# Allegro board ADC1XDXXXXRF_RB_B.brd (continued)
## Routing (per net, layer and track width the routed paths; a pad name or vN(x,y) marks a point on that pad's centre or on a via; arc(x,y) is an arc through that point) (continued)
FMC_DCLK_DQD+: length 142.2
  TOP w0.102: v1(121.71,103.76) 122.22,104.25 U5.A9
  SIG3 w0.102: v3(58.34,90.25) 58.17,90.25 58.12,90.3 58.12,107.54 60.91,110.34 118.52,110.34 121.11,107.75 121.11,105.5 122.11,104.5 122.11,103.87 121.99,103.76 v1(121.71,103.76)
  BOTTOM w0.102: FMC.F4 14.48,74.88 48.19,74.88 58.14,84.83 58.14,90.04 v3(58.34,90.25)
FMC_DCLK_DQD-: length 142.1
  TOP w0.102: U5.B9 122.22,103.25 v1(122.71,103.76)
  SIG3 w0.102: v1(122.71,103.76) 122.31,104.15 122.31,104.59 121.31,105.59 121.31,107.83 118.6,110.54 60.82,110.54 57.91,107.63 57.91,90.47 v3(57.68,90.25)
  BOTTOM w0.102: FMC.F5 14.48,75.13 48.08,75.13 57.89,84.94 57.89,90.04 v3(57.68,90.25)
FMC_DI+0: length 142.1
  TOP w0.102: U5.N7 120.2,92.25 v1(119.71,91.75)
  SIG2 w0.102: v3(10.79,96.6) 11.33,97.13 46.08,97.13 46.18,97.03 46.18,95.7 46.4,95.48 46.77,95.48 46.99,95.7 46.99,97.03 47.09,97.13 47.29,97.13 47.4,97.03 47.4,95.7 47.62,95.48 47.99,95.48 48.21,95.7 48.21,97.03 48.31,97.13 48.51,97.13 48.62,97.03 48.62,95.7 48.84,95.48 49.21,95.48 49.43,95.7 49.43,97.03 49.53,97.13 49.73,97.13 49.83,97.03 49.83,95.7 50.06,95.48 50.43,95.48 50.65,95.7 50.65,97.03 50.75,97.13 50.95,97.13 51.05,97.03 51.05,95.7 51.27,95.48 51.65,95.48 51.87,95.7 51.87,97.03 51.97,97.13 52.17,97.13 52.27,97.03 52.27,95.7 52.49,95.48 52.87,95.48 53.09,95.7 53.09,97.03 53.19,97.13 53.39,97.13 53.49,97.03 53.49,95.7 53.71,95.48 54.08,95.48 54.31,95.7 54.31,97.03 54.41,97.13 54.61,97.13 54.71,97.03 54.71,95.7 54.93,95.48 55.3,95.48 55.52,95.7 55.52,97.03 55.63,97.13 55.83,97.13 55.93,97.03 55.93,95.72 56.15,95.5 56.52,95.5 56.74,95.72 56.74,97.03 56.85,97.13 57.05,97.13 57.15,97.03 57.15,95.72 57.37,95.5 57.74,95.5 57.96,95.72 57.96,97.03 58.06,97.13 98.77,97.13 103.75,92.15 119.21,92.15 119.31,92.15 v1(119.71,91.75)
  BOTTOM w0.102: FMC.C22 v3(10.79,96.6)
FMC_DI+1: length 142.1
  TOP w0.102: U5.M6 119.2,93.25 v1(118.71,92.75)
  SIG1 w0.102: v1(118.71,92.75) 118.28,92.75 117.67,92.15 116.54,92.15 116.31,91.92 116.31,91.49 115.96,91.15 115.53,91.15 115.31,90.92 115.31,90.37 115.09,90.14 106.53,90.14 98.27,98.4 93.33,98.4 93.11,98.62 93.11,98.91 93.01,99.01 92.81,99.01 92.7,98.91 92.7,98.62 92.48,98.4 92.11,98.4 91.89,98.62 91.89,98.91 91.79,99.01 91.59,99.01 91.48,98.91 91.48,98.62 91.26,98.4 90.89,98.4 90.67,98.62 90.67,98.91 90.57,99.01 90.37,99.01 90.27,98.91 90.27,98.62 90.05,98.4 89.67,98.4 89.45,98.62 89.45,98.91 89.35,99.01 89.15,99.01 89.05,98.91 89.05,98.62 88.83,98.4 88.45,98.4 88.23,98.62 88.23,98.91 88.13,99.01 87.93,99.01 87.83,98.91 87.83,98.62 87.61,98.4 87.24,98.4 87.01,98.62 87.01,98.91 86.91,99.01 86.71,99.01 86.61,98.91 86.61,98.62 86.39,98.4 86.02,98.4 85.8,98.62 85.8,98.91 85.69,99.01 85.49,99.01 85.39,98.91 85.39,98.62 85.17,98.4 84.8,98.4 84.58,98.62 84.58,98.91 84.47,99.01 84.27,99.01 84.17,98.91 84.17,98.62 83.95,98.4 83.58,98.4 83.36,98.62 83.36,98.91 83.26,99.01 83.05,99.01 82.95,98.91 82.95,98.62 82.73,98.4 82.36,98.4 82.14,98.62 82.14,98.91 82.04,99.01 81.83,99.01 81.73,98.91 81.73,98.62 81.51,98.4 81.14,98.4 80.92,98.62 80.92,98.91 80.82,99.01 80.61,99.01 80.51,98.91 80.51,98.62 80.29,98.4 79.92,98.4 79.7,98.62 79.7,98.91 79.6,99.01 79.39,99.01 79.29,98.91 79.29,98.62 79.07,98.4 78.7,98.4 78.48,98.62 78.48,98.91 78.38,99.01 78.18,99.01 78.07,98.91 78.07,98.62 77.85,98.4 77.48,98.4 77.26,98.62 77.26,98.91 77.16,99.01 76.96,99.01 76.85,98.91 76.85,98.62 76.63,98.4 76.26,98.4 76.04,98.62 76.04,98.91 75.94,99.01 75.74,99.01 75.64,98.91 75.64,98.62 75.41,98.4 75.04,98.4 74.82,98.62 74.82,98.91 74.72,99.01 74.52,99.01 74.42,98.91 74.42,98.62 74.2,98.4 73.82,98.4 73.6,98.62 73.6,98.91 73.5,99.01 73.3,99.01 73.2,98.91 73.2,98.62 72.98,98.4 72.6,98.4 72.38,98.62 72.38,98.91 72.28,99.01 72.08,99.01 71.98,98.91 71.98,98.62 71.76,98.4 71.39,98.4 71.16,98.62 71.16,98.91 71.06,99.01 70.86,99.01 70.76,98.91 70.76,98.62 70.54,98.4 70.17,98.4 69.95,98.62 69.95,98.91 69.84,99.01 69.64,99.01 69.54,98.91 69.54,98.62 69.32,98.4 68.95,98.4 68.73,98.62 68.73,98.91 68.62,99.01 68.42,99.01 68.32,98.91 68.32,98.62 68.1,98.4 67.73,98.4 67.51,98.62 67.51,98.91 67.41,99.01 67.2,99.01 67.1,98.91 67.1,98.62 66.88,98.4 66.51,98.4 66.29,98.62 66.29,98.91 66.19,99.01 65.98,99.01 65.88,98.91 65.88,98.62 65.66,98.4 65.29,98.4 65.07,98.62 65.07,98.91 64.97,99.01 64.76,99.01 64.66,98.91 64.66,98.62 64.44,98.4 64.07,98.4 63.85,98.62 63.85,98.91 63.75,99.01 63.54,99.01 63.44,98.91 63.44,98.62 63.22,98.4 62.85,98.4 62.63,98.62 62.63,98.91 62.53,99.01 62.33,99.01 62.22,98.91 62.22,98.62 62,98.4 61.63,98.4 61.41,98.62 61.41,98.91 61.31,99.01 61.11,99.01 61,98.91 61,98.62 60.78,98.4 60.41,98.4 60.19,98.62 60.19,98.93 60.09,99.03 59.89,99.03 59.79,98.93 59.79,98.62 59.57,98.4 59.19,98.4 58.97,98.62 58.97,98.93 58.87,99.03 58.67,99.03 58.57,98.93 58.57,98.62 58.35,98.4 57.97,98.4 57.75,98.62 57.75,98.93 57.65,99.03 57.45,99.03 57.35,98.93 57.35,98.62 57.13,98.4 56.76,98.4 56.53,98.62 56.53,98.93 56.43,99.03 56.23,99.03 56.13,98.93 56.13,98.62 55.91,98.4 55.54,98.4 55.32,98.62 55.32,98.93 55.21,99.03 55.01,99.03 54.91,98.93 54.91,98.62 54.69,98.4 54.32,98.4 54.1,98.62 54.1,98.93 53.99,99.03 53.79,99.03 53.69,98.93 53.69,98.62 53.47,98.4 53.1,98.4 52.88,98.62 52.88,98.93 52.78,99.03 52.57,99.03 52.47,98.93 52.47,98.62 52.25,98.4 51.88,98.4 51.66,98.62 51.66,98.93 51.56,99.03 51.35,99.03 51.25,98.93 51.25,98.62 51.03,98.4 50.66,98.4 50.44,98.62 50.44,98.93 50.34,99.03 50.13,99.03 50.03,98.93 50.03,98.62 49.81,98.4 49.44,98.4 49.22,98.62 49.22,98.93 49.12,99.03 48.91,99.03 48.81,98.93 48.81,98.62 48.59,98.4 48.22,98.4 48,98.62 48,98.93 47.9,99.03 47.7,99.03 47.59,98.93 47.59,98.62 47.37,98.4 47,98.4 46.78,98.62 46.78,98.93 46.68,99.03 46.48,99.03 46.37,98.93 46.37,98.62 46.15,98.4 17.35,98.4 17.14,98.2 v3(17.14,97.87)
  BOTTOM w0.102: FMC.H22 v3(17.14,97.87)
FMC_DI+2: length 142.1
  TOP w0.102: v1(117.71,91.75) 118.2,92.25 U5.N5
  SIG1 w0.102: v1(117.71,91.75) 117.31,91.35 117.31,90.48 116.98,90.14 116.51,90.14 116.32,89.95 116.32,89.36 116.1,89.14 105.75,89.14 97.76,97.13 95.77,97.13 95.55,97.35 95.55,97.59 95.45,97.69 95.24,97.69 95.14,97.59 95.14,97.35 94.92,97.13 94.55,97.13 94.33,97.35 94.33,97.59 94.23,97.69 94.02,97.69 93.92,97.59 93.92,97.35 93.7,97.13 93.33,97.13 93.11,97.35 93.11,97.59 93.01,97.69 92.81,97.69 92.7,97.59 92.7,97.35 92.48,97.13 92.11,97.13 91.89,97.35 91.89,97.61 91.79,97.71 91.59,97.71 91.48,97.61 91.48,97.35 91.26,97.13 90.89,97.13 90.67,97.35 90.67,97.61 90.57,97.71 90.37,97.71 90.27,97.61 90.27,97.35 90.05,97.13 89.67,97.13 89.45,97.35 89.45,97.61 89.35,97.71 89.15,97.71 89.05,97.61 89.05,97.35 88.83,97.13 88.45,97.13 88.23,97.35 88.23,97.61 88.13,97.71 87.93,97.71 87.83,97.61 87.83,97.35 87.61,97.13 87.24,97.13 87.01,97.35 87.01,97.61 86.91,97.71 86.71,97.71 86.61,97.61 86.61,97.35 86.39,97.13 86.02,97.13 85.8,97.35 85.8,97.61 85.69,97.71 85.49,97.71 85.39,97.61 85.39,97.35 85.17,97.13 84.8,97.13 84.58,97.35 84.58,97.61 84.47,97.71 84.27,97.71 84.17,97.61 84.17,97.35 83.95,97.13 83.58,97.13 83.36,97.35 83.36,97.61 83.26,97.71 83.05,97.71 82.95,97.61 82.95,97.35 82.73,97.13 82.36,97.13 82.14,97.35 82.14,97.61 82.04,97.71 81.83,97.71 81.73,97.61 81.73,97.35 81.51,97.13 81.14,97.13 80.92,97.35 80.92,97.61 80.82,97.71 80.61,97.71 80.51,97.61 80.51,97.35 80.29,97.13 79.92,97.13 79.7,97.35 79.7,97.61 79.6,97.71 79.39,97.71 79.29,97.61 79.29,97.35 79.07,97.13 78.7,97.13 78.48,97.35 78.48,97.61 78.38,97.71 78.18,97.71 78.07,97.61 78.07,97.35 77.85,97.13 77.48,97.13 77.26,97.35 77.26,97.61 77.16,97.71 76.96,97.71 76.85,97.61 76.85,97.35 76.63,97.13 76.26,97.13 76.04,97.35 76.04,97.61 75.94,97.71 75.74,97.71 75.64,97.61 75.64,97.35 75.41,97.13 75.04,97.13 74.82,97.35 74.82,97.61 74.72,97.71 74.52,97.71 74.42,97.61 74.42,97.35 74.2,97.13 73.82,97.13 73.6,97.35 73.6,97.61 73.5,97.71 73.3,97.71 73.2,97.61 73.2,97.35 72.98,97.13 72.6,97.13 72.38,97.35 72.38,97.61 72.28,97.71 72.08,97.71 71.98,97.61 71.98,97.35 71.76,97.13 71.39,97.13 71.16,97.35 71.16,97.61 71.06,97.71 70.86,97.71 70.76,97.61 70.76,97.35 70.54,97.13 70.17,97.13 69.95,97.35 69.95,97.61 69.84,97.71 69.64,97.71 69.54,97.61 69.54,97.35 69.32,97.13 68.95,97.13 68.73,97.35 68.73,97.61 68.62,97.71 68.42,97.71 68.32,97.61 68.32,97.35 68.1,97.13 67.73,97.13 67.51,97.35 67.51,97.61 67.41,97.71 67.2,97.71 67.1,97.61 67.1,97.35 66.88,97.13 66.51,97.13 66.29,97.35 66.29,97.61 66.19,97.71 65.98,97.71 65.88,97.61 65.88,97.35 65.66,97.13 65.29,97.13 65.07,97.35 65.07,97.61 64.97,97.71 64.76,97.71 64.66,97.61 64.66,97.35 64.44,97.13 64.07,97.13 63.85,97.35 63.85,97.61 63.75,97.71 63.54,97.71 63.44,97.61 63.44,97.35 63.22,97.13 62.85,97.13 62.63,97.35 62.63,97.61 62.53,97.71 62.33,97.71 62.22,97.61 62.22,97.35 62,97.13 61.63,97.13 61.41,97.35 61.41,97.61 61.31,97.71 61.11,97.71 61,97.61 61,97.35 60.78,97.13 60.41,97.13 60.19,97.35 60.19,97.61 60.09,97.71 59.89,97.71 59.79,97.61 59.79,97.35 59.57,97.13 59.19,97.13 58.97,97.35 58.97,97.61 58.87,97.71 58.67,97.71 58.57,97.61 58.57,97.35 58.35,97.13 57.97,97.13 57.75,97.35 57.75,97.61 57.65,97.71 57.45,97.71 57.35,97.61 57.35,97.35 57.13,97.13 56.76,97.13 56.53,97.35 56.53,97.61 56.43,97.71 56.23,97.71 56.13,97.61 56.13,97.35 55.91,97.13 55.54,97.13 55.32,97.35 55.32,97.61 55.21,97.71 55.01,97.71 54.91,97.61 54.91,97.35 54.69,97.13 54.32,97.13 54.1,97.35 54.1,97.61 53.99,97.71 53.79,97.71 53.69,97.61 53.69,97.35 53.47,97.13 53.1,97.13 52.88,97.35 52.88,97.61 52.78,97.71 52.57,97.71 52.47,97.61 52.47,97.35 52.25,97.13 51.88,97.13 51.66,97.35 51.66,97.61 51.56,97.71 51.35,97.71 51.25,97.61 51.25,97.35 51.03,97.13 50.66,97.13 50.44,97.35 50.44,97.61 50.34,97.71 50.13,97.71 50.03,97.61 50.03,97.35 49.81,97.13 49.44,97.13 49.22,97.35 49.22,97.61 49.12,97.71 48.91,97.71 48.81,97.61 48.81,97.35 48.59,97.13 48.22,97.13 48,97.35 48,97.61 47.9,97.71 47.7,97.71 47.59,97.61 47.59,97.35 47.37,97.13 47,97.13 46.78,97.35 46.78,97.61 46.68,97.71 46.48,97.71 46.37,97.61 46.37,97.35 46.15,97.13 15.62,97.13 15.49,97 15.49,96.7 15.6,96.6 v3(15.88,96.6)
  BOTTOM w0.102: FMC.G21 v3(15.88,96.6)
FMC_DI+3: length 142.2
  TOP w0.102: U5.M4 117.2,93.25 v1(116.71,92.75)
  SIG1 w0.102: v1(116.71,92.75) 116.29,92.75 115.87,92.33 115.57,92.33 115.39,92.15 108.13,92.15 98.07,102.21 95.77,102.21 95.55,102.43 95.55,102.72 95.45,102.82 95.24,102.82 95.14,102.72 95.14,102.43 94.92,102.21 94.55,102.21 94.33,102.43 94.33,102.72 94.23,102.82 94.02,102.82 93.92,102.72 93.92,102.43 93.7,102.21 93.33,102.21 93.11,102.43 93.11,102.72 93.01,102.82 92.81,102.82 92.7,102.72 92.7,102.43 92.48,102.21 92.11,102.21 91.89,102.43 91.89,102.72 91.79,102.82 91.59,102.82 91.48,102.72 91.48,102.43 91.26,102.21 90.89,102.21 90.67,102.43 90.67,102.72 90.57,102.82 90.37,102.82 90.27,102.72 90.27,102.43 90.05,102.21 89.67,102.21 89.45,102.43 89.45,102.72 89.35,102.82 89.15,102.82 89.05,102.72 89.05,102.43 88.83,102.21 88.45,102.21 88.23,102.43 88.23,102.72 88.13,102.82 87.93,102.82 87.83,102.72 87.83,102.43 87.61,102.21 87.24,102.21 87.01,102.43 87.01,102.72 86.91,102.82 86.71,102.82 86.61,102.72 86.61,102.43 86.39,102.21 86.02,102.21 85.8,102.43 85.8,102.72 85.69,102.82 85.49,102.82 85.39,102.72 85.39,102.43 85.17,102.21 84.8,102.21 84.58,102.43 84.58,102.74 84.47,102.84 84.27,102.84 84.17,102.74 84.17,102.43 83.95,102.21 83.58,102.21 83.36,102.43 83.36,102.74 83.26,102.84 83.05,102.84 82.95,102.74 82.95,102.43 82.73,102.21 82.36,102.21 82.14,102.43 82.14,102.74 82.04,102.84 81.83,102.84 81.73,102.74 81.73,102.43 81.51,102.21 81.14,102.21 80.92,102.43 80.92,102.74 80.82,102.84 80.61,102.84 80.51,102.74 80.51,102.43 80.29,102.21 79.92,102.21 79.7,102.43 79.7,102.74 79.6,102.84 79.39,102.84 79.29,102.74 79.29,102.43 79.07,102.21 78.7,102.21 78.48,102.43 78.48,102.74 78.38,102.84 78.18,102.84 78.07,102.74 78.07,102.43 77.85,102.21 77.48,102.21 77.26,102.43 77.26,102.74 77.16,102.84 76.96,102.84 76.85,102.74 76.85,102.43 76.63,102.21 76.26,102.21 76.04,102.43 76.04,102.74 75.94,102.84 75.74,102.84 75.64,102.74 75.64,102.43 75.41,102.21 75.04,102.21 74.82,102.43 74.82,102.74 74.72,102.84 74.52,102.84 74.42,102.74 74.42,102.43 74.2,102.21 73.82,102.21 73.6,102.43 73.6,102.74 73.5,102.84 73.3,102.84 73.2,102.74 73.2,102.43 72.98,102.21 72.6,102.21 72.38,102.43 72.38,102.74 72.28,102.84 72.08,102.84 71.98,102.74 71.98,102.43 71.76,102.21 71.39,102.21 71.16,102.43 71.16,102.74 71.06,102.84 70.86,102.84 70.76,102.74 70.76,102.43 70.54,102.21 70.17,102.21 69.95,102.43 69.95,102.74 69.84,102.84 69.64,102.84 69.54,102.74 69.54,102.43 69.32,102.21 68.95,102.21 68.73,102.43 68.73,102.74 68.62,102.84 68.42,102.84 68.32,102.74 68.32,102.43 68.1,102.21 67.73,102.21 67.51,102.43 67.51,102.74 67.41,102.84 67.2,102.84 67.1,102.74 67.1,102.43 66.88,102.21 66.51,102.21 66.29,102.43 66.29,102.74 66.19,102.84 65.98,102.84 65.88,102.74 65.88,102.43 65.66,102.21 65.29,102.21 65.07,102.43 65.07,102.74 64.97,102.84 64.76,102.84 64.66,102.74 64.66,102.43 64.44,102.21 64.07,102.21 63.85,102.43 63.85,102.74 63.75,102.84 63.54,102.84 63.44,102.74 63.44,102.43 63.22,102.21 62.85,102.21 62.63,102.43 62.63,102.74 62.53,102.84 62.33,102.84 62.22,102.74 62.22,102.43 62,102.21 61.63,102.21 61.41,102.43 61.41,102.74 61.31,102.84 61.11,102.84 61,102.74 61,102.43 60.78,102.21 60.41,102.21 60.19,102.43 60.19,102.74 60.09,102.84 59.89,102.84 59.79,102.74 59.79,102.43 59.57,102.21 59.19,102.21 58.97,102.43 58.97,102.74 58.87,102.84 58.67,102.84 58.57,102.74 58.57,102.43 58.35,102.21 57.97,102.21 57.75,102.43 57.75,102.74 57.65,102.84 57.45,102.84 57.35,102.74 57.35,102.43 57.13,102.21 56.76,102.21 56.53,102.43 56.53,102.74 56.43,102.84 56.23,102.84 56.13,102.74 56.13,102.43 55.91,102.21 55.54,102.21 55.32,102.43 55.32,102.74 55.21,102.84 55.01,102.84 54.91,102.74 54.91,102.43 54.69,102.21 54.32,102.21 54.1,102.43 54.1,102.74 53.99,102.84 53.79,102.84 53.69,102.74 53.69,102.43 53.47,102.21 53.1,102.21 52.88,102.43 52.88,102.74 52.78,102.84 52.57,102.84 52.47,102.74 52.47,102.43 52.25,102.21 51.88,102.21 51.66,102.43 51.66,102.74 51.56,102.84 51.35,102.84 51.25,102.74 51.25,102.43 51.03,102.21 50.66,102.21 50.44,102.43 50.44,102.74 50.34,102.84 50.13,102.84 50.03,102.74 50.03,102.43 49.81,102.21 49.44,102.21 49.22,102.43 49.22,102.74 49.12,102.84 48.91,102.84 48.81,102.74 48.81,102.43 48.59,102.21 48.22,102.21 48,102.43 48,102.74 47.9,102.84 47.7,102.84 47.59,102.74 47.59,102.43 47.37,102.21 47,102.21 46.78,102.43 46.78,102.74 46.68,102.84 46.48,102.84 46.37,102.74 46.37,102.43 46.15,102.21 17.35,102.21 17.14,102.01 v3(17.14,101.68)
  BOTTOM w0.102: FMC.H25 v3(17.14,101.68)
FMC_DI+4: length 142.1
  TOP w0.102: v1(115.7,91.75) 116.2,92.25 U5.N3
  SIG1 w0.102: v1(115.7,91.75) 115.27,91.75 114.83,91.31 114.56,91.31 114.56,91.31 114.39,91.15 107.45,91.15 97.66,100.94 96.99,100.94 96.77,101.16 96.77,101.45 96.67,101.55 96.46,101.55 96.36,101.45 96.36,101.16 96.14,100.94 95.77,100.94 95.55,101.16 95.55,101.45 95.45,101.55 95.24,101.55 95.14,101.45 95.14,101.16 94.92,100.94 94.55,100.94 94.33,101.16 94.33,101.45 94.23,101.55 94.02,101.55 93.92,101.45 93.92,101.16 93.7,100.94 93.33,100.94 93.11,101.16 93.11,101.45 93.01,101.55 92.81,101.55 92.7,101.45 92.7,101.16 92.48,100.94 92.11,100.94 91.89,101.16 91.89,101.45 91.79,101.55 91.59,101.55 91.48,101.45 91.48,101.16 91.26,100.94 90.89,100.94 90.67,101.16 90.67,101.45 90.57,101.55 90.37,101.55 90.27,101.45 90.27,101.16 90.05,100.94 89.67,100.94 89.45,101.16 89.45,101.45 89.35,101.55 89.15,101.55 89.05,101.45 89.05,101.16 88.83,100.94 88.45,100.94 88.23,101.16 88.23,101.45 88.13,101.55 87.93,101.55 87.83,101.45 87.83,101.16 87.61,100.94 87.24,100.94 87.01,101.16 87.01,101.45 86.91,101.55 86.71,101.55 86.61,101.45 86.61,101.16 86.39,100.94 86.02,100.94 85.8,101.16 85.8,101.45 85.69,101.55 85.49,101.55 85.39,101.45 85.39,101.16 85.17,100.94 84.8,100.94 84.58,101.16 84.58,101.45 84.47,101.55 84.27,101.55 84.17,101.45 84.17,101.16 83.95,100.94 83.58,100.94 83.36,101.16 83.36,101.45 83.26,101.55 83.05,101.55 82.95,101.45 82.95,101.16 82.73,100.94 82.36,100.94 82.14,101.16 82.14,101.45 82.04,101.55 81.83,101.55 81.73,101.45 81.73,101.16 81.51,100.94 81.14,100.94 80.92,101.16 80.92,101.45 80.82,101.55 80.61,101.55 80.51,101.45 80.51,101.16 80.29,100.94 79.92,100.94 79.7,101.16 79.7,101.45 79.6,101.55 79.39,101.55 79.29,101.45 79.29,101.16 79.07,100.94 78.7,100.94 78.48,101.16 78.48,101.45 78.38,101.55 78.18,101.55 78.07,101.45 78.07,101.16 77.85,100.94 77.48,100.94 77.26,101.16 77.26,101.45 77.16,101.55 76.96,101.55 76.85,101.45 76.85,101.16 76.63,100.94 76.26,100.94 76.04,101.16 76.04,101.45 75.94,101.55 75.74,101.55 75.64,101.45 75.64,101.16 75.41,100.94 75.04,100.94 74.82,101.16 74.82,101.45 74.72,101.55 74.52,101.55 74.42,101.45 74.42,101.16 74.2,100.94 73.82,100.94 73.6,101.16 73.6,101.45 73.5,101.55 73.3,101.55 73.2,101.45 73.2,101.16 72.98,100.94 72.6,100.94 72.38,101.16 72.38,101.45 72.28,101.55 72.08,101.55 71.98,101.45 71.98,101.16 71.76,100.94 71.39,100.94 71.16,101.16 71.16,101.45 71.06,101.55 70.86,101.55 70.76,101.45 70.76,101.16 70.54,100.94 70.17,100.94 69.95,101.16 69.95,101.45 69.84,101.55 69.64,101.55 69.54,101.45 69.54,101.16 69.32,100.94 68.95,100.94 68.73,101.16 68.73,101.45 68.62,101.55 68.42,101.55 68.32,101.45 68.32,101.16 68.1,100.94 67.73,100.94 67.51,101.16 67.51,101.45 67.41,101.55 67.2,101.55 67.1,101.45 67.1,101.16 66.88,100.94 66.51,100.94 66.29,101.16 66.29,101.45 66.19,101.55 65.98,101.55 65.88,101.45 65.88,101.16 65.66,100.94 65.29,100.94 65.07,101.16 65.07,101.45 64.97,101.55 64.76,101.55 64.66,101.45 64.66,101.16 64.44,100.94 64.07,100.94 63.85,101.16 63.85,101.45 63.75,101.55 63.54,101.55 63.44,101.45 63.44,101.16 63.22,100.94 62.85,100.94 62.63,101.16 62.63,101.45 62.53,101.55 62.33,101.55 62.22,101.45 62.22,101.16 62,100.94 61.63,100.94 61.41,101.16 61.41,101.45 61.31,101.55 61.11,101.55 61,101.45 61,101.16 60.78,100.94 60.41,100.94 60.19,101.16 60.19,101.47 60.09,101.57 59.89,101.57 59.79,101.47 59.79,101.16 59.57,100.94 59.19,100.94 58.97,101.16 58.97,101.47 58.87,101.57 58.67,101.57 58.57,101.47 58.57,101.16 58.35,100.94 57.97,100.94 57.75,101.16 57.75,101.47 57.65,101.57 57.45,101.57 57.35,101.47 57.35,101.16 57.13,100.94 56.76,100.94 56.53,101.16 56.53,101.47 56.43,101.57 56.23,101.57 56.13,101.47 56.13,101.16 55.91,100.94 55.54,100.94 55.32,101.16 55.32,101.47 55.21,101.57 55.01,101.57 54.91,101.47 54.91,101.16 54.69,100.94 54.32,100.94 54.1,101.16 54.1,101.47 53.99,101.57 53.79,101.57 53.69,101.47 53.69,101.16 53.47,100.94 53.1,100.94 52.88,101.16 52.88,101.47 52.78,101.57 52.57,101.57 52.47,101.47 52.47,101.16 52.25,100.94 51.88,100.94 51.66,101.16 51.66,101.47 51.56,101.57 51.35,101.57 51.25,101.47 51.25,101.16 51.03,100.94 50.66,100.94 50.44,101.16 50.44,101.47 50.34,101.57 50.13,101.57 50.03,101.47 50.03,101.16 49.81,100.94 49.44,100.94 49.22,101.16 49.22,101.47 49.12,101.57 48.91,101.57 48.81,101.47 48.81,101.16 48.59,100.94 48.22,100.94 48,101.16 48,101.47 47.9,101.57 47.7,101.57 47.59,101.47 47.59,101.16 47.37,100.94 47,100.94 46.78,101.16 46.78,101.47 46.68,101.57 46.48,101.57 46.37,101.47 46.37,101.16 46.15,100.94 16.08,100.94 15.88,100.74 v3(15.88,100.41)
  BOTTOM w0.102: FMC.G24 v3(15.88,100.41)
FMC_DI+5: length 142.1
  TOP w0.102: U5.M2 115.2,93.25 v1(114.7,92.75)
  SIG2 w0.102: v1(114.7,92.75) 114.29,92.75 113.69,93.35 104.25,93.35 98.99,98.6 61.72,98.6 61.62,98.7 61.62,99.73 61.4,99.95 61.03,99.95 60.81,99.73 60.81,98.7 60.71,98.6 60.5,98.6 60.4,98.7 60.4,99.73 60.18,99.95 59.81,99.95 59.59,99.73 59.59,98.7 59.49,98.6 59.28,98.6 59.18,98.7 59.18,99.73 58.96,99.95 58.59,99.95 58.37,99.73 58.37,98.7 58.27,98.6 58.06,98.6 57.96,98.7 57.96,99.75 57.74,99.97 57.37,99.97 57.15,99.75 57.15,98.7 57.05,98.6 56.85,98.6 56.74,98.7 56.74,99.75 56.52,99.97 56.15,99.97 55.93,99.75 55.93,98.7 55.83,98.6 55.63,98.6 55.52,98.7 55.52,99.75 55.3,99.97 54.93,99.97 54.71,99.75 54.71,98.7 54.61,98.6 54.41,98.6 54.31,98.7 54.31,99.75 54.08,99.97 53.71,99.97 53.49,99.75 53.49,98.7 53.39,98.6 53.19,98.6 53.09,98.7 53.09,99.75 52.87,99.97 52.49,99.97 52.27,99.75 52.27,98.7 52.17,98.6 51.97,98.6 51.87,98.7 51.87,99.75 51.65,99.97 51.27,99.97 51.05,99.75 51.05,98.7 50.95,98.6 50.75,98.6 50.65,98.7 50.65,99.75 50.43,99.97 50.06,99.97 49.83,99.75 49.83,98.7 49.73,98.6 49.53,98.6 49.43,98.7 49.43,99.75 49.21,99.97 48.84,99.97 48.62,99.75 48.62,98.7 48.51,98.6 48.31,98.6 48.21,98.7 48.21,99.75 47.99,99.97 47.62,99.97 47.4,99.75 47.4,98.7 47.29,98.6 47.09,98.6 46.99,98.7 46.99,99.75 46.77,99.97 46.4,99.97 46.18,99.75 46.18,98.7 46.08,98.6 10.36,98.6 10.2,98.77 10.2,99.55 10.32,99.67 11.53,99.67 v3(12.06,99.14)
  BOTTOM w0.102: v3(12.06,99.14) FMC.D23
FMC_DI+6: length 142.1
  TOP w0.102: U5.L7 120.2,94.24 v1(119.71,93.75)
  SIG3 w0.102: v3(80.04,92.79) 80.08,92.79 80.64,93.35 116.44,93.35 117.44,94.35 119.1,94.35 v1(119.71,93.75)
  BOTTOM w0.102: FMC.H28 17.04,104.32 17.04,103.2 17.42,102.82 45.32,102.82 46.91,104.42 46.91,109.5 47.85,110.44 49.63,110.44 49.73,110.34 49.73,108.86 49.98,108.61 50.4,108.61 50.65,108.86 50.65,110.34 50.75,110.44 50.95,110.44 51.06,110.34 51.06,108.86 51.31,108.61 51.72,108.61 51.97,108.86 51.97,110.34 52.07,110.44 52.27,110.44 52.38,110.34 52.38,108.86 52.63,108.61 53.04,108.61 53.29,108.86 53.29,110.34 53.39,110.44 53.6,110.44 53.7,110.34 53.7,108.86 53.95,108.61 54.36,108.61 54.61,108.86 54.61,110.34 54.71,110.44 54.92,110.44 55.02,110.34 55.02,108.86 55.27,108.61 55.68,108.61 55.93,108.86 55.93,110.34 56.03,110.44 72.87,110.44 80.04,103.28 v3(80.04,92.79)
FMC_DI+7: length 142.2
  TOP w0.102: v1(119.69,94.74) U5.K7
  SIG2 w0.102: v1(119.69,94.74) 119.28,94.74 118.87,94.34 118.57,94.34 118.12,94.78 118.12,95.93 117.9,96.14 104.42,96.14 97.08,103.48 93.34,103.48 93.12,103.7 93.12,103.94 93.01,104.04 92.81,104.04 92.71,103.94 92.71,103.7 92.49,103.48 92.12,103.48 91.9,103.7 91.9,103.94 91.8,104.04 91.59,104.04 91.49,103.94 91.49,103.7 91.27,103.48 90.9,103.48 90.68,103.7 90.68,103.94 90.58,104.04 90.37,104.04 90.27,103.94 90.27,103.7 90.05,103.48 89.68,103.48 89.46,103.7 89.46,103.94 89.36,104.04 89.15,104.04 89.05,103.94 89.05,103.7 88.83,103.48 88.46,103.48 88.24,103.7 88.24,103.94 88.14,104.04 87.93,104.04 87.83,103.94 87.83,103.7 87.61,103.48 87.24,103.48 87.02,103.7 87.02,103.96 86.92,104.06 86.72,104.06 86.61,103.96 86.61,103.7 86.39,103.48 86.02,103.48 85.8,103.7 85.8,103.96 85.7,104.06 85.5,104.06 85.39,103.96 85.39,103.7 85.17,103.48 84.8,103.48 84.58,103.7 84.58,103.96 84.48,104.06 84.28,104.06 84.18,103.96 84.18,103.7 83.96,103.48 83.58,103.48 83.36,103.7 83.36,103.96 83.26,104.06 83.06,104.06 82.96,103.96 82.96,103.7 82.74,103.48 82.36,103.48 82.14,103.7 82.14,103.96 82.04,104.06 81.84,104.06 81.74,103.96 81.74,103.7 81.52,103.48 81.14,103.48 80.92,103.7 80.92,103.96 80.82,104.06 80.62,104.06 80.52,103.96 80.52,103.7 80.3,103.48 79.93,103.48 79.71,103.7 79.71,103.96 79.6,104.06 79.4,104.06 79.3,103.96 79.3,103.7 79.08,103.48 78.71,103.48 78.49,103.7 78.49,103.96 78.38,104.06 78.18,104.06 78.08,103.96 78.08,103.7 77.86,103.48 77.49,103.48 77.27,103.7 77.27,103.96 77.17,104.06 76.96,104.06 76.86,103.96 76.86,103.7 76.64,103.48 76.27,103.48 76.05,103.7 76.05,103.96 75.95,104.06 75.74,104.06 75.64,103.96 75.64,103.7 75.42,103.48 75.05,103.48 74.83,103.7 74.83,103.96 74.73,104.06 74.52,104.06 74.42,103.96 74.42,103.7 74.2,103.48 73.83,103.48 73.61,103.7 73.61,103.96 73.51,104.06 73.3,104.06 73.2,103.96 73.2,103.7 72.98,103.48 72.61,103.48 72.39,103.7 72.39,103.96 72.29,104.06 72.09,104.06 71.98,103.96 71.98,103.7 71.76,103.48 71.39,103.48 71.17,103.7 71.17,103.96 71.07,104.06 70.87,104.06 70.76,103.96 70.76,103.7 70.54,103.48 70.17,103.48 69.95,103.7 69.95,103.96 69.85,104.06 69.65,104.06 69.55,103.96 69.55,103.7 69.32,103.48 68.95,103.48 68.73,103.7 68.73,103.96 68.63,104.06 68.43,104.06 68.33,103.96 68.33,103.7 68.11,103.48 67.73,103.48 67.51,103.7 67.51,103.96 67.41,104.06 67.21,104.06 67.11,103.96 67.11,103.7 66.89,103.48 66.51,103.48 66.29,103.7 66.29,103.96 66.19,104.06 65.99,104.06 65.89,103.96 65.89,103.7 65.67,103.48 65.3,103.48 65.07,103.7 65.07,103.96 64.97,104.06 64.77,104.06 64.67,103.96 64.67,103.7 64.45,103.48 64.08,103.48 63.86,103.7 63.86,103.96 63.75,104.06 63.55,104.06 63.45,103.96 63.45,103.7 63.23,103.48 62.86,103.48 62.64,103.7 62.64,103.96 62.53,104.06 62.33,104.06 62.23,103.96 62.23,103.7 62.01,103.48 61.64,103.48 61.42,103.7 61.42,103.96 61.32,104.06 61.11,104.06 61.01,103.96 61.01,103.7 60.79,103.48 60.42,103.48 60.2,103.7 60.2,103.96 60.1,104.06 59.89,104.06 59.79,103.96 59.79,103.7 59.57,103.48 59.2,103.48 58.98,103.7 58.98,103.96 58.88,104.06 58.67,104.06 58.57,103.96 58.57,103.7 58.35,103.48 57.98,103.48 57.76,103.7 57.76,103.96 57.66,104.06 57.45,104.06 57.35,103.96 57.35,103.7 57.13,103.48 56.76,103.48 56.54,103.7 56.54,103.96 56.44,104.06 56.24,104.06 56.13,103.96 56.13,103.7 55.91,103.48 55.54,103.48 55.32,103.7 55.32,103.96 55.22,104.06 55.02,104.06 54.91,103.96 54.91,103.7 54.69,103.48 54.32,103.48 54.1,103.7 54.1,103.96 54,104.06 53.8,104.06 53.7,103.96 53.7,103.7 53.48,103.48 53.1,103.48 52.88,103.7 52.88,103.96 52.78,104.06 52.58,104.06 52.48,103.96 52.48,103.7 52.26,103.48 51.88,103.48 51.66,103.7 51.66,103.96 51.56,104.06 51.36,104.06 51.26,103.96 51.26,103.7 51.04,103.48 50.66,103.48 50.44,103.7 50.44,103.96 50.34,104.06 50.14,104.06 50.04,103.96 50.04,103.7 49.82,103.48 49.45,103.48 49.23,103.7 49.23,103.96 49.12,104.06 48.92,104.06 48.82,103.96 48.82,103.7 48.6,103.48 48.23,103.48 48.01,103.7 48.01,103.96 47.9,104.06 47.7,104.06 47.6,103.96 47.6,103.7 47.38,103.48 47.01,103.48 46.79,103.7 46.79,103.96 46.69,104.06 46.48,104.06 46.38,103.96 46.38,103.7 46.16,103.48 15.14,103.48 v3(14.61,102.95)
  BOTTOM w0.102: FMC.G27 v3(14.61,102.95)
FMC_DI+8: length 142.1
  TOP w0.102: v1(117.72,94.74) U5.K5
  SIG2 w0.102: v3(10.79,101.68) 11.33,102.21 46.16,102.21 46.38,102.43 46.38,102.72 46.48,102.82 46.69,102.82 46.79,102.72 46.79,102.43 47.01,102.21 47.38,102.21 47.6,102.43 47.6,102.72 47.7,102.82 47.9,102.82 48.01,102.72 48.01,102.43 48.23,102.21 48.6,102.21 48.82,102.43 48.82,102.72 48.92,102.82 49.12,102.82 49.23,102.72 49.23,102.43 49.45,102.21 49.82,102.21 50.04,102.43 50.04,102.72 50.14,102.82 50.34,102.82 50.44,102.72 50.44,102.43 50.66,102.21 51.04,102.21 51.26,102.43 51.26,102.72 51.36,102.82 51.56,102.82 51.66,102.72 51.66,102.43 51.88,102.21 52.26,102.21 52.48,102.43 52.48,102.72 52.58,102.82 52.78,102.82 52.88,102.72 52.88,102.43 53.1,102.21 53.48,102.21 53.7,102.43 53.7,102.72 53.8,102.82 54,102.82 54.1,102.72 54.1,102.43 54.32,102.21 54.69,102.21 54.91,102.43 54.91,102.72 55.02,102.82 55.22,102.82 55.32,102.72 55.32,102.43 55.54,102.21 55.91,102.21 56.13,102.43 56.13,102.72 56.24,102.82 56.44,102.82 56.54,102.72 56.54,102.43 56.76,102.21 57.13,102.21 57.35,102.43 57.35,102.72 57.45,102.82 57.66,102.82 57.76,102.72 57.76,102.43 57.98,102.21 58.35,102.21 58.57,102.43 58.57,102.72 58.67,102.82 58.88,102.82 58.98,102.72 58.98,102.43 59.2,102.21 59.57,102.21 59.79,102.43 59.79,102.72 59.89,102.82 60.1,102.82 60.2,102.72 60.2,102.43 60.42,102.21 60.79,102.21 61.01,102.43 61.01,102.72 61.11,102.82 61.32,102.82 61.42,102.72 61.42,102.43 61.64,102.21 62.01,102.21 62.23,102.43 62.23,102.72 62.33,102.82 62.53,102.82 62.64,102.72 62.64,102.43 62.86,102.21 63.23,102.21 63.45,102.43 63.45,102.72 63.55,102.82 63.75,102.82 63.86,102.72 63.86,102.43 64.08,102.21 64.45,102.21 64.67,102.43 64.67,102.72 64.77,102.82 64.97,102.82 65.07,102.72 65.07,102.43 65.3,102.21 65.67,102.21 65.89,102.43 65.89,102.72 65.99,102.82 66.19,102.82 66.29,102.72 66.29,102.43 66.51,102.21 66.89,102.21 67.11,102.43 67.11,102.72 67.21,102.82 67.41,102.82 67.51,102.72 67.51,102.43 67.73,102.21 68.11,102.21 68.33,102.43 68.33,102.72 68.43,102.82 68.63,102.82 68.73,102.72 68.73,102.43 68.95,102.21 69.32,102.21 69.55,102.43 69.55,102.72 69.65,102.82 69.85,102.82 69.95,102.72 69.95,102.43 70.17,102.21 70.54,102.21 70.76,102.43 70.76,102.72 70.87,102.82 71.07,102.82 71.17,102.72 71.17,102.43 71.39,102.21 71.76,102.21 71.98,102.43 71.98,102.72 72.09,102.82 72.29,102.82 72.39,102.72 72.39,102.43 72.61,102.21 72.98,102.21 73.2,102.43 73.2,102.72 73.3,102.82 73.51,102.82 73.61,102.72 73.61,102.43 73.83,102.21 74.2,102.21 74.42,102.43 74.42,102.72 74.52,102.82 74.73,102.82 74.83,102.72 74.83,102.43 75.05,102.21 75.42,102.21 75.64,102.43 75.64,102.72 75.74,102.82 75.95,102.82 76.05,102.72 76.05,102.43 76.27,102.21 76.64,102.21 76.86,102.43 76.86,102.72 76.96,102.82 77.17,102.82 77.27,102.72 77.27,102.43 77.49,102.21 77.86,102.21 78.08,102.43 78.08,102.72 78.18,102.82 78.38,102.82 78.49,102.72 78.49,102.43 78.71,102.21 79.08,102.21 79.3,102.43 79.3,102.72 79.4,102.82 79.6,102.82 79.71,102.72 79.71,102.43 79.93,102.21 80.3,102.21 80.52,102.43 80.52,102.74 80.62,102.84 80.82,102.84 80.92,102.74 80.92,102.43 81.14,102.21 81.52,102.21 81.74,102.43 81.74,102.74 81.84,102.84 82.04,102.84 82.14,102.74 82.14,102.43 82.36,102.21 82.74,102.21 82.96,102.43 82.96,102.72 83.06,102.82 83.26,102.82 83.36,102.72 83.36,102.43 83.58,102.21 83.96,102.21 84.18,102.43 84.18,102.74 84.28,102.84 84.48,102.84 84.58,102.74 84.58,102.43 84.8,102.21 85.17,102.21 85.39,102.43 85.39,102.74 85.5,102.84 85.7,102.84 85.8,102.74 85.8,102.43 86.02,102.21 86.39,102.21 86.61,102.43 86.61,102.74 86.72,102.84 86.92,102.84 87.02,102.74 87.02,102.43 87.24,102.21 87.61,102.21 87.83,102.43 87.83,102.74 87.93,102.84 88.14,102.84 88.24,102.74 88.24,102.43 88.46,102.21 97.21,102.21 104.27,95.14 116.04,95.14 116.32,94.86 116.32,94.58 116.56,94.34 117.31,94.34 v1(117.72,94.74)
  BOTTOM w0.102: FMC.D26 v3(10.79,101.68)
FMC_DI+9: length 142.1
  TOP w0.102: v1(117.72,95.75) U5.J5
  SIG1 w0.102: v1(117.72,95.75) 117.32,95.35 117.32,94.4 116.06,93.14 108.68,93.14 98.35,103.48 88.45,103.48 88.23,103.7 88.23,103.94 88.13,104.04 87.93,104.04 87.83,103.94 87.83,103.7 87.61,103.48 87.24,103.48 87.01,103.7 87.01,103.94 86.91,104.04 86.71,104.04 86.61,103.94 86.61,103.7 86.39,103.48 86.02,103.48 85.8,103.7 85.8,103.94 85.69,104.04 85.49,104.04 85.39,103.94 85.39,103.7 85.17,103.48 84.8,103.48 84.58,103.7 84.58,103.94 84.47,104.04 84.27,104.04 84.17,103.94 84.17,103.7 83.95,103.48 83.58,103.48 83.36,103.7 83.36,103.94 83.26,104.04 83.05,104.04 82.95,103.94 82.95,103.7 82.73,103.48 82.36,103.48 82.14,103.7 82.14,103.96 82.04,104.06 81.83,104.06 81.73,103.96 81.73,103.7 81.51,103.48 81.14,103.48 80.92,103.7 80.92,103.96 80.82,104.06 80.61,104.06 80.51,103.96 80.51,103.7 80.29,103.48 79.92,103.48 79.7,103.7 79.7,103.96 79.6,104.06 79.39,104.06 79.29,103.96 79.29,103.7 79.07,103.48 78.7,103.48 78.48,103.7 78.48,103.96 78.38,104.06 78.18,104.06 78.07,103.96 78.07,103.7 77.85,103.48 77.48,103.48 77.26,103.7 77.26,103.96 77.16,104.06 76.96,104.06 76.85,103.96 76.85,103.7 76.63,103.48 76.26,103.48 76.04,103.7 76.04,103.96 75.94,104.06 75.74,104.06 75.64,103.96 75.64,103.7 75.41,103.48 75.04,103.48 74.82,103.7 74.82,103.96 74.72,104.06 74.52,104.06 74.42,103.96 74.42,103.7 74.2,103.48 73.82,103.48 73.6,103.7 73.6,103.96 73.5,104.06 73.3,104.06 73.2,103.96 73.2,103.7 72.98,103.48 72.6,103.48 72.38,103.7 72.38,103.96 72.28,104.06 72.08,104.06 71.98,103.96 71.98,103.7 71.76,103.48 71.39,103.48 71.16,103.7 71.16,103.96 71.06,104.06 70.86,104.06 70.76,103.96 70.76,103.7 70.54,103.48 70.17,103.48 69.95,103.7 69.95,103.96 69.84,104.06 69.64,104.06 69.54,103.96 69.54,103.7 69.32,103.48 68.95,103.48 68.73,103.7 68.73,103.96 68.62,104.06 68.42,104.06 68.32,103.96 68.32,103.7 68.1,103.48 67.73,103.48 67.51,103.7 67.51,103.96 67.41,104.06 67.2,104.06 67.1,103.96 67.1,103.7 66.88,103.48 66.51,103.48 66.29,103.7 66.29,103.96 66.19,104.06 65.98,104.06 65.88,103.96 65.88,103.7 65.66,103.48 65.29,103.48 65.07,103.7 65.07,103.96 64.97,104.06 64.76,104.06 64.66,103.96 64.66,103.7 64.44,103.48 64.07,103.48 63.85,103.7 63.85,103.96 63.75,104.06 63.54,104.06 63.44,103.96 63.44,103.7 63.22,103.48 62.85,103.48 62.63,103.7 62.63,103.96 62.53,104.06 62.33,104.06 62.22,103.96 62.22,103.7 62,103.48 61.63,103.48 61.41,103.7 61.41,103.96 61.31,104.06 61.11,104.06 61,103.96 61,103.7 60.78,103.48 60.41,103.48 60.19,103.7 60.19,103.96 60.09,104.06 59.89,104.06 59.79,103.96 59.79,103.7 59.57,103.48 59.19,103.48 58.97,103.7 58.97,103.96 58.87,104.06 58.67,104.06 58.57,103.96 58.57,103.7 58.35,103.48 57.97,103.48 57.75,103.7 57.75,103.96 57.65,104.06 57.45,104.06 57.35,103.96 57.35,103.7 57.13,103.48 56.76,103.48 56.53,103.7 56.53,103.96 56.43,104.06 56.23,104.06 56.13,103.96 56.13,103.7 55.91,103.48 55.54,103.48 55.32,103.7 55.32,103.96 55.21,104.06 55.01,104.06 54.91,103.96 54.91,103.7 54.69,103.48 54.32,103.48 54.1,103.7 54.1,103.96 53.99,104.06 53.79,104.06 53.69,103.96 53.69,103.7 53.47,103.48 53.1,103.48 52.88,103.7 52.88,103.96 52.78,104.06 52.57,104.06 52.47,103.96 52.47,103.7 52.25,103.48 51.88,103.48 51.66,103.7 51.66,103.96 51.56,104.06 51.35,104.06 51.25,103.96 51.25,103.7 51.03,103.48 50.66,103.48 50.44,103.7 50.44,103.96 50.34,104.06 50.13,104.06 50.03,103.96 50.03,103.7 49.81,103.48 49.44,103.48 49.22,103.7 49.22,103.96 49.12,104.06 48.91,104.06 48.81,103.96 48.81,103.7 48.59,103.48 48.22,103.48 48,103.7 48,103.96 47.9,104.06 47.7,104.06 47.59,103.96 47.59,103.7 47.37,103.48 47,103.48 46.78,103.7 46.78,103.96 46.68,104.06 46.48,104.06 46.37,103.96 46.37,103.7 46.15,103.48 11.33,103.48 v3(10.79,102.95)
  BOTTOM w0.102: FMC.C26 v3(10.79,102.95)
FMC_DI+10: length 142
  TOP w0.102: U5.L1 113.85,94.62 113.33,94.62 112.83,95.12 111.98,95.12 v1(111.61,94.74)
  SIG1 w0.102: v3(15.88,108.03) 16.41,108.56 16.74,108.56 18.01,107.29 47.35,107.29 47.57,107.51 47.57,108.89 47.67,108.99 47.87,108.99 47.97,108.89 47.97,107.51 48.2,107.29 48.57,107.29 48.79,107.51 48.79,108.89 48.89,108.99 49.09,108.99 49.19,108.89 49.19,107.51 49.41,107.29 49.79,107.29 50.01,107.51 50.01,108.89 50.11,108.99 50.31,108.99 50.41,108.89 50.41,107.51 50.63,107.29 51.01,107.29 51.23,107.51 51.23,108.89 51.33,108.99 51.53,108.99 51.63,108.89 51.63,107.51 51.85,107.29 52.22,107.29 52.45,107.51 52.45,108.89 52.55,108.99 52.75,108.99 52.85,108.89 52.85,107.51 53.07,107.29 53.44,107.29 53.66,107.51 53.66,108.89 53.77,108.99 53.97,108.99 54.07,108.89 54.07,107.51 54.29,107.29 54.66,107.29 54.88,107.51 54.88,108.89 54.99,108.99 55.19,108.99 55.29,108.89 55.29,107.51 55.51,107.29 55.88,107.29 56.1,107.51 56.1,108.89 56.2,108.99 56.41,108.99 56.51,108.89 56.51,107.51 56.73,107.29 57.1,107.29 57.32,107.51 57.32,108.89 57.42,108.99 57.63,108.99 57.73,108.89 57.73,107.51 57.95,107.29 58.32,107.29 58.54,107.51 58.54,108.89 58.64,108.99 58.85,108.99 58.95,108.89 58.95,107.51 59.17,107.29 59.54,107.29 59.76,107.51 59.76,108.89 59.86,108.99 60.07,108.99 60.17,108.89 60.17,107.51 60.39,107.29 60.76,107.29 60.98,107.51 60.98,108.89 61.08,108.99 61.28,108.99 61.39,108.89 61.39,107.51 61.61,107.29 97.87,107.29 110.01,95.14 111.21,95.14 v1(111.61,94.74)
  BOTTOM w0.102: FMC.H31 v3(15.88,108.03)
FMC_DI+11: length 142.1
  TOP w0.102: v1(115.72,94.74) U5.K3
  SIG3 w0.102: v1(115.72,94.74) 115.12,94.15 83.43,94.15 83.06,94.51 82.75,94.51 82.6,94.36 v3(82.6,93.95)
  BOTTOM w0.102: v3(82.6,93.95) 82.4,94.16 82.4,103.51 73.94,111.96 57.2,111.96 57.1,112.06 57.1,113.26 56.85,113.51 56.44,113.51 56.19,113.26 56.19,112.06 56.08,111.96 55.88,111.96 55.78,112.06 55.78,113.26 55.53,113.51 55.11,113.51 54.86,113.26 54.86,112.06 54.76,111.96 54.56,111.96 54.46,112.06 54.46,113.26 54.21,113.51 53.79,113.51 53.54,113.26 53.54,112.06 53.44,111.96 53.24,111.96 53.14,112.06 53.14,113.26 52.89,113.51 52.47,113.51 52.22,113.26 52.22,112.06 52.12,111.96 51.92,111.96 51.82,112.06 51.82,113.26 51.57,113.51 51.15,113.51 50.9,113.26 50.9,112.06 50.8,111.96 50.6,111.96 50.5,112.06 50.5,113.29 50.25,113.54 49.83,113.54 49.58,113.29 49.58,112.06 49.48,111.96 49.28,111.96 49.18,112.06 49.18,113.29 48.92,113.54 48.51,113.54 48.26,113.29 48.26,112.06 48.16,111.96 47.96,111.96 47.85,112.06 47.85,113.29 47.6,113.54 47.19,113.54 46.94,113.29 46.94,112.06 46.84,111.96 14.83,111.96 14.48,111.61 14.48,108.15 FMC.G30
FMC_DI-0: length 142.1
  TOP w0.102: U5.M7 120.21,93.25 v1(119.71,92.75)
  SIG2 w0.102: v3(10.79,97.87) 11.33,97.33 46.16,97.33 46.38,97.11 46.38,95.78 46.48,95.68 46.69,95.68 46.79,95.78 46.79,97.11 47.01,97.33 47.38,97.33 47.6,97.11 47.6,95.78 47.7,95.68 47.9,95.68 48.01,95.78 48.01,97.11 48.23,97.33 48.6,97.33 48.82,97.11 48.82,95.78 48.92,95.68 49.12,95.68 49.23,95.78 49.23,97.11 49.45,97.33 49.82,97.33 50.04,97.11 50.04,95.78 50.14,95.68 50.34,95.68 50.44,95.78 50.44,97.11 50.66,97.33 51.04,97.33 51.26,97.11 51.26,95.78 51.36,95.68 51.56,95.68 51.66,95.78 51.66,97.11 51.88,97.33 52.26,97.33 52.48,97.11 52.48,95.78 52.58,95.68 52.78,95.68 52.88,95.78 52.88,97.11 53.1,97.33 53.48,97.33 53.7,97.11 53.7,95.78 53.8,95.68 54,95.68 54.1,95.78 54.1,97.11 54.32,97.33 54.69,97.33 54.91,97.11 54.91,95.78 55.02,95.68 55.22,95.68 55.32,95.78 55.32,97.11 55.54,97.33 55.91,97.33 56.13,97.11 56.13,95.81 56.24,95.71 56.44,95.71 56.54,95.81 56.54,97.11 56.76,97.33 57.13,97.33 57.35,97.11 57.35,95.81 57.45,95.71 57.66,95.71 57.76,95.81 57.76,97.11 57.98,97.33 98.86,97.33 103.84,92.35 119.31,92.35 v1(119.71,92.75)
  BOTTOM w0.102: FMC.C23 v3(10.79,97.87)
FMC_DI-1: length 142.1
  TOP w0.102: v1(117.71,92.75) 118.2,93.25 U5.M5
  SIG1 w0.102: v1(117.71,92.75) 117.31,92.35 116.45,92.35 116.1,92 116.1,91.58 115.88,91.35 115.45,91.35 115.1,91.01 115.1,90.45 115,90.35 106.61,90.35 98.36,98.6 93.42,98.6 93.31,98.7 93.31,98.99 93.09,99.21 92.72,99.21 92.5,98.99 92.5,98.7 92.4,98.6 92.2,98.6 92.09,98.7 92.09,98.99 91.87,99.21 91.5,99.21 91.28,98.99 91.28,98.7 91.18,98.6 90.98,98.6 90.88,98.7 90.88,98.99 90.65,99.21 90.28,99.21 90.06,98.99 90.06,98.7 89.96,98.6 89.76,98.6 89.66,98.7 89.66,98.99 89.44,99.21 89.06,99.21 88.84,98.99 88.84,98.7 88.74,98.6 88.54,98.6 88.44,98.7 88.44,98.99 88.22,99.21 87.84,99.21 87.62,98.99 87.62,98.7 87.52,98.6 87.32,98.6 87.22,98.7 87.22,98.99 87,99.21 86.63,99.21 86.4,98.99 86.4,98.7 86.3,98.6 86.1,98.6 86,98.7 86,98.99 85.78,99.21 85.41,99.21 85.19,98.99 85.19,98.7 85.08,98.6 84.88,98.6 84.78,98.7 84.78,98.99 84.56,99.21 84.19,99.21 83.97,98.99 83.97,98.7 83.86,98.6 83.66,98.6 83.56,98.7 83.56,98.99 83.34,99.21 82.97,99.21 82.75,98.99 82.75,98.7 82.65,98.6 82.44,98.6 82.34,98.7 82.34,98.99 82.12,99.21 81.75,99.21 81.53,98.99 81.53,98.7 81.43,98.6 81.22,98.6 81.12,98.7 81.12,98.99 80.9,99.21 80.53,99.21 80.31,98.99 80.31,98.7 80.21,98.6 80,98.6 79.9,98.7 79.9,98.99 79.68,99.21 79.31,99.21 79.09,98.99 79.09,98.7 78.99,98.6 78.78,98.6 78.68,98.7 78.68,98.99 78.46,99.21 78.09,99.21 77.87,98.99 77.87,98.7 77.77,98.6 77.57,98.6 77.46,98.7 77.46,98.99 77.24,99.21 76.87,99.21 76.65,98.99 76.65,98.7 76.55,98.6 76.35,98.6 76.24,98.7 76.24,98.99 76.02,99.21 75.65,99.21 75.43,98.99 75.43,98.7 75.33,98.6 75.13,98.6 75.03,98.7 75.03,98.99 74.81,99.21 74.43,99.21 74.21,98.99 74.21,98.7 74.11,98.6 73.91,98.6 73.81,98.7 73.81,98.99 73.59,99.21 73.21,99.21 72.99,98.99 72.99,98.7 72.89,98.6 72.69,98.6 72.59,98.7 72.59,98.99 72.37,99.21 72,99.21 71.77,98.99 71.77,98.7 71.67,98.6 71.47,98.6 71.37,98.7 71.37,98.99 71.15,99.21 70.78,99.21 70.56,98.99 70.56,98.7 70.45,98.6 70.25,98.6 70.15,98.7 70.15,98.99 69.93,99.21 69.56,99.21 69.34,98.99 69.34,98.7 69.23,98.6 69.03,98.6 68.93,98.7 68.93,98.99 68.71,99.21 68.34,99.21 68.12,98.99 68.12,98.7 68.02,98.6 67.81,98.6 67.71,98.7 67.71,98.99 67.49,99.21 67.12,99.21 66.9,98.99 66.9,98.7 66.8,98.6 66.59,98.6 66.49,98.7 66.49,98.99 66.27,99.21 65.9,99.21 65.68,98.99 65.68,98.7 65.58,98.6 65.37,98.6 65.27,98.7 65.27,98.99 65.05,99.21 64.68,99.21 64.46,98.99 64.46,98.7 64.36,98.6 64.15,98.6 64.05,98.7 64.05,98.99 63.83,99.21 63.46,99.21 63.24,98.99 63.24,98.7 63.14,98.6 62.94,98.6 62.83,98.7 62.83,98.99 62.61,99.21 62.24,99.21 62.02,98.99 62.02,98.7 61.92,98.6 61.72,98.6 61.61,98.7 61.61,98.99 61.39,99.21 61.02,99.21 60.8,98.99 60.8,98.7 60.7,98.6 60.5,98.6 60.4,98.7 60.4,99.02 60.17,99.24 59.8,99.24 59.58,99.02 59.58,98.7 59.48,98.6 59.28,98.6 59.18,98.7 59.18,99.02 58.96,99.24 58.58,99.24 58.36,99.02 58.36,98.7 58.26,98.6 58.06,98.6 57.96,98.7 57.96,99.02 57.74,99.24 57.36,99.24 57.14,99.02 57.14,98.7 57.04,98.6 56.84,98.6 56.74,98.7 56.74,99.02 56.52,99.24 56.15,99.24 55.92,99.02 55.92,98.7 55.82,98.6 55.62,98.6 55.52,98.7 55.52,99.02 55.3,99.24 54.93,99.24 54.71,99.02 54.71,98.7 54.6,98.6 54.4,98.6 54.3,98.7 54.3,99.02 54.08,99.24 53.71,99.24 53.49,99.02 53.49,98.7 53.38,98.6 53.18,98.6 53.08,98.7 53.08,99.02 52.86,99.24 52.49,99.24 52.27,99.02 52.27,98.7 52.17,98.6 51.96,98.6 51.86,98.7 51.86,99.02 51.64,99.24 51.27,99.24 51.05,99.02 51.05,98.7 50.95,98.6 50.74,98.6 50.64,98.7 50.64,99.02 50.42,99.24 50.05,99.24 49.83,99.02 49.83,98.7 49.73,98.6 49.52,98.6 49.42,98.7 49.42,99.02 49.2,99.24 48.83,99.24 48.61,99.02 48.61,98.7 48.51,98.6 48.3,98.6 48.2,98.7 48.2,99.02 47.98,99.24 47.61,99.24 47.39,99.02 47.39,98.7 47.29,98.6 47.09,98.6 46.98,98.7 46.98,99.02 46.76,99.24 46.39,99.24 46.17,99.02 46.17,98.7 46.07,98.6 16.41,98.6 v3(15.88,99.14)
  BOTTOM w0.102: FMC.H23 v3(15.88,99.14)
FMC_DI-2: length 142.1
  TOP w0.102: v1(116.71,91.75) 117.2,92.25 U5.N4
  SIG1 w0.102: v1(116.71,91.75) 117.1,91.35 117.1,90.56 116.89,90.35 116.43,90.35 116.12,90.04 116.12,89.45 116.01,89.35 105.83,89.35 97.85,97.33 95.85,97.33 95.75,97.43 95.75,97.67 95.53,97.89 95.16,97.89 94.94,97.67 94.94,97.43 94.84,97.33 94.63,97.33 94.53,97.43 94.53,97.67 94.31,97.89 93.94,97.89 93.72,97.67 93.72,97.43 93.62,97.33 93.42,97.33 93.31,97.43 93.31,97.67 93.09,97.89 92.72,97.89 92.5,97.67 92.5,97.43 92.4,97.33 92.2,97.33 92.09,97.43 92.09,97.7 91.87,97.92 91.5,97.92 91.28,97.7 91.28,97.43 91.18,97.33 90.98,97.33 90.88,97.43 90.88,97.7 90.65,97.92 90.28,97.92 90.06,97.7 90.06,97.43 89.96,97.33 89.76,97.33 89.66,97.43 89.66,97.7 89.44,97.92 89.06,97.92 88.84,97.7 88.84,97.43 88.74,97.33 88.54,97.33 88.44,97.43 88.44,97.7 88.22,97.92 87.84,97.92 87.62,97.7 87.62,97.43 87.52,97.33 87.32,97.33 87.22,97.43 87.22,97.7 87,97.92 86.63,97.92 86.4,97.7 86.4,97.43 86.3,97.33 86.1,97.33 86,97.43 86,97.7 85.78,97.92 85.41,97.92 85.19,97.7 85.19,97.43 85.08,97.33 84.88,97.33 84.78,97.43 84.78,97.7 84.56,97.92 84.19,97.92 83.97,97.7 83.97,97.43 83.86,97.33 83.66,97.33 83.56,97.43 83.56,97.7 83.34,97.92 82.97,97.92 82.75,97.7 82.75,97.43 82.65,97.33 82.44,97.33 82.34,97.43 82.34,97.7 82.12,97.92 81.75,97.92 81.53,97.7 81.53,97.43 81.43,97.33 81.22,97.33 81.12,97.43 81.12,97.7 80.9,97.92 80.53,97.92 80.31,97.7 80.31,97.43 80.21,97.33 80,97.33 79.9,97.43 79.9,97.7 79.68,97.92 79.31,97.92 79.09,97.7 79.09,97.43 78.99,97.33 78.78,97.33 78.68,97.43 78.68,97.7 78.46,97.92 78.09,97.92 77.87,97.7 77.87,97.43 77.77,97.33 77.57,97.33 77.46,97.43 77.46,97.7 77.24,97.92 76.87,97.92 76.65,97.7 76.65,97.43 76.55,97.33 76.35,97.33 76.24,97.43 76.24,97.7 76.02,97.92 75.65,97.92 75.43,97.7 75.43,97.43 75.33,97.33 75.13,97.33 75.03,97.43 75.03,97.7 74.81,97.92 74.43,97.92 74.21,97.7 74.21,97.43 74.11,97.33 73.91,97.33 73.81,97.43 73.81,97.7 73.59,97.92 73.21,97.92 72.99,97.7 72.99,97.43 72.89,97.33 72.69,97.33 72.59,97.43 72.59,97.7 72.37,97.92 72,97.92 71.77,97.7 71.77,97.43 71.67,97.33 71.47,97.33 71.37,97.43 71.37,97.7 71.15,97.92 70.78,97.92 70.56,97.7 70.56,97.43 70.45,97.33 70.25,97.33 70.15,97.43 70.15,97.7 69.93,97.92 69.56,97.92 69.34,97.7 69.34,97.43 69.23,97.33 69.03,97.33 68.93,97.43 68.93,97.7 68.71,97.92 68.34,97.92 68.12,97.7 68.12,97.43 68.02,97.33 67.81,97.33 67.71,97.43 67.71,97.7 67.49,97.92 67.12,97.92 66.9,97.7 66.9,97.43 66.8,97.33 66.59,97.33 66.49,97.43 66.49,97.7 66.27,97.92 65.9,97.92 65.68,97.7 65.68,97.43 65.58,97.33 65.37,97.33 65.27,97.43 65.27,97.7 65.05,97.92 64.68,97.92 64.46,97.7 64.46,97.43 64.36,97.33 64.15,97.33 64.05,97.43 64.05,97.7 63.83,97.92 63.46,97.92 63.24,97.7 63.24,97.43 63.14,97.33 62.94,97.33 62.83,97.43 62.83,97.7 62.61,97.92 62.24,97.92 62.02,97.7 62.02,97.43 61.92,97.33 61.72,97.33 61.61,97.43 61.61,97.7 61.39,97.92 61.02,97.92 60.8,97.7 60.8,97.43 60.7,97.33 60.5,97.33 60.4,97.43 60.4,97.7 60.17,97.92 59.8,97.92 59.58,97.7 59.58,97.43 59.48,97.33 59.28,97.33 59.18,97.43 59.18,97.7 58.96,97.92 58.58,97.92 58.36,97.7 58.36,97.43 58.26,97.33 58.06,97.33 57.96,97.43 57.96,97.7 57.74,97.92 57.36,97.92 57.14,97.7 57.14,97.43 57.04,97.33 56.84,97.33 56.74,97.43 56.74,97.7 56.52,97.92 56.15,97.92 55.92,97.7 55.92,97.43 55.82,97.33 55.62,97.33 55.52,97.43 55.52,97.7 55.3,97.92 54.93,97.92 54.71,97.7 54.71,97.43 54.6,97.33 54.4,97.33 54.3,97.43 54.3,97.7 54.08,97.92 53.71,97.92 53.49,97.7 53.49,97.43 53.38,97.33 53.18,97.33 53.08,97.43 53.08,97.7 52.86,97.92 52.49,97.92 52.27,97.7 52.27,97.43 52.17,97.33 51.96,97.33 51.86,97.43 51.86,97.7 51.64,97.92 51.27,97.92 51.05,97.7 51.05,97.43 50.95,97.33 50.74,97.33 50.64,97.43 50.64,97.7 50.42,97.92 50.05,97.92 49.83,97.7 49.83,97.43 49.73,97.33 49.52,97.33 49.42,97.43 49.42,97.7 49.2,97.92 48.83,97.92 48.61,97.7 48.61,97.43 48.51,97.33 48.3,97.33 48.2,97.43 48.2,97.7 47.98,97.92 47.61,97.92 47.39,97.7 47.39,97.43 47.29,97.33 47.09,97.33 46.98,97.43 46.98,97.7 46.76,97.92 46.39,97.92 46.17,97.7 46.17,97.43 46.07,97.33 15.14,97.33 v3(14.61,97.87)
  BOTTOM w0.102: FMC.G22 v3(14.61,97.87)
FMC_DI-3: length 142.1
  TOP w0.102: v1(115.7,92.75) 116.2,93.25 U5.M3
  SIG1 w0.102: v1(115.7,92.75) 115.31,92.35 108.22,92.35 98.15,102.41 95.85,102.41 95.75,102.51 95.75,102.8 95.53,103.02 95.16,103.02 94.94,102.8 94.94,102.51 94.84,102.41 94.63,102.41 94.53,102.51 94.53,102.8 94.31,103.02 93.94,103.02 93.72,102.8 93.72,102.51 93.62,102.41 93.42,102.41 93.31,102.51 93.31,102.8 93.09,103.02 92.72,103.02 92.5,102.8 92.5,102.51 92.4,102.41 92.2,102.41 92.09,102.51 92.09,102.8 91.87,103.02 91.5,103.02 91.28,102.8 91.28,102.51 91.18,102.41 90.98,102.41 90.88,102.51 90.88,102.8 90.65,103.02 90.28,103.02 90.06,102.8 90.06,102.51 89.96,102.41 89.76,102.41 89.66,102.51 89.66,102.8 89.44,103.02 89.06,103.02 88.84,102.8 88.84,102.51 88.74,102.41 88.54,102.41 88.44,102.51 88.44,102.8 88.22,103.02 87.84,103.02 87.62,102.8 87.62,102.51 87.52,102.41 87.32,102.41 87.22,102.51 87.22,102.8 87,103.02 86.63,103.02 86.4,102.8 86.4,102.51 86.3,102.41 86.1,102.41 86,102.51 86,102.8 85.78,103.02 85.41,103.02 85.19,102.8 85.19,102.51 85.08,102.41 84.88,102.41 84.78,102.51 84.78,102.83 84.56,103.05 84.19,103.05 83.97,102.83 83.97,102.51 83.86,102.41 83.66,102.41 83.56,102.51 83.56,102.83 83.34,103.05 82.97,103.05 82.75,102.83 82.75,102.51 82.65,102.41 82.44,102.41 82.34,102.51 82.34,102.83 82.12,103.05 81.75,103.05 81.53,102.83 81.53,102.51 81.43,102.41 81.22,102.41 81.12,102.51 81.12,102.83 80.9,103.05 80.53,103.05 80.31,102.83 80.31,102.51 80.21,102.41 80,102.41 79.9,102.51 79.9,102.83 79.68,103.05 79.31,103.05 79.09,102.83 79.09,102.51 78.99,102.41 78.78,102.41 78.68,102.51 78.68,102.83 78.46,103.05 78.09,103.05 77.87,102.83 77.87,102.51 77.77,102.41 77.57,102.41 77.46,102.51 77.46,102.83 77.24,103.05 76.87,103.05 76.65,102.83 76.65,102.51 76.55,102.41 76.35,102.41 76.24,102.51 76.24,102.83 76.02,103.05 75.65,103.05 75.43,102.83 75.43,102.51 75.33,102.41 75.13,102.41 75.03,102.51 75.03,102.83 74.81,103.05 74.43,103.05 74.21,102.83 74.21,102.51 74.11,102.41 73.91,102.41 73.81,102.51 73.81,102.83 73.59,103.05 73.21,103.05 72.99,102.83 72.99,102.51 72.89,102.41 72.69,102.41 72.59,102.51 72.59,102.83 72.37,103.05 72,103.05 71.77,102.83 71.77,102.51 71.67,102.41 71.47,102.41 71.37,102.51 71.37,102.83 71.15,103.05 70.78,103.05 70.56,102.83 70.56,102.51 70.45,102.41 70.25,102.41 70.15,102.51 70.15,102.83 69.93,103.05 69.56,103.05 69.34,102.83 69.34,102.51 69.23,102.41 69.03,102.41 68.93,102.51 68.93,102.83 68.71,103.05 68.34,103.05 68.12,102.83 68.12,102.51 68.02,102.41 67.81,102.41 67.71,102.51 67.71,102.83 67.49,103.05 67.12,103.05 66.9,102.83 66.9,102.51 66.8,102.41 66.59,102.41 66.49,102.51 66.49,102.83 66.27,103.05 65.9,103.05 65.68,102.83 65.68,102.51 65.58,102.41 65.37,102.41 65.27,102.51 65.27,102.83 65.05,103.05 64.68,103.05 64.46,102.83 64.46,102.51 64.36,102.41 64.15,102.41 64.05,102.51 64.05,102.83 63.83,103.05 63.46,103.05 63.24,102.83 63.24,102.51 63.14,102.41 62.94,102.41 62.83,102.51 62.83,102.83 62.61,103.05 62.24,103.05 62.02,102.83 62.02,102.51 61.92,102.41 61.72,102.41 61.61,102.51 61.61,102.83 61.39,103.05 61.02,103.05 60.8,102.83 60.8,102.51 60.7,102.41 60.5,102.41 60.4,102.51 60.4,102.83 60.17,103.05 59.8,103.05 59.58,102.83 59.58,102.51 59.48,102.41 59.28,102.41 59.18,102.51 59.18,102.83 58.96,103.05 58.58,103.05 58.36,102.83 58.36,102.51 58.26,102.41 58.06,102.41 57.96,102.51 57.96,102.83 57.74,103.05 57.36,103.05 57.14,102.83 57.14,102.51 57.04,102.41 56.84,102.41 56.74,102.51 56.74,102.83 56.52,103.05 56.15,103.05 55.92,102.83 55.92,102.51 55.82,102.41 55.62,102.41 55.52,102.51 55.52,102.83 55.3,103.05 54.93,103.05 54.71,102.83 54.71,102.51 54.6,102.41 54.4,102.41 54.3,102.51 54.3,102.83 54.08,103.05 53.71,103.05 53.49,102.83 53.49,102.51 53.38,102.41 53.18,102.41 53.08,102.51 53.08,102.83 52.86,103.05 52.49,103.05 52.27,102.83 52.27,102.51 52.17,102.41 51.96,102.41 51.86,102.51 51.86,102.83 51.64,103.05 51.27,103.05 51.05,102.83 51.05,102.51 50.95,102.41 50.74,102.41 50.64,102.51 50.64,102.83 50.42,103.05 50.05,103.05 49.83,102.83 49.83,102.51 49.73,102.41 49.52,102.41 49.42,102.51 49.42,102.83 49.2,103.05 48.83,103.05 48.61,102.83 48.61,102.51 48.51,102.41 48.3,102.41 48.2,102.51 48.2,102.83 47.98,103.05 47.61,103.05 47.39,102.83 47.39,102.51 47.29,102.41 47.09,102.41 46.98,102.51 46.98,102.83 46.76,103.05 46.39,103.05 46.17,102.83 46.17,102.51 46.07,102.41 16.41,102.41 v3(15.88,102.95)
  BOTTOM w0.102: FMC.H26 v3(15.88,102.95)
FMC_DI-4: length 142.1
  TOP w0.102: v1(114.7,91.75) 115.2,92.25 U5.N2
  SIG1 w0.102: v1(114.7,91.75) 114.31,91.35 107.54,91.35 97.75,101.14 97.07,101.14 96.97,101.24 96.97,101.53 96.75,101.75 96.38,101.75 96.16,101.53 96.16,101.24 96.06,101.14 95.85,101.14 95.75,101.24 95.75,101.53 95.53,101.75 95.16,101.75 94.94,101.53 94.94,101.24 94.84,101.14 94.63,101.14 94.53,101.24 94.53,101.53 94.31,101.75 93.94,101.75 93.72,101.53 93.72,101.24 93.62,101.14 93.42,101.14 93.31,101.24 93.31,101.53 93.09,101.75 92.72,101.75 92.5,101.53 92.5,101.24 92.4,101.14 92.2,101.14 92.09,101.24 92.09,101.53 91.87,101.75 91.5,101.75 91.28,101.53 91.28,101.24 91.18,101.14 90.98,101.14 90.88,101.24 90.88,101.53 90.65,101.75 90.28,101.75 90.06,101.53 90.06,101.24 89.96,101.14 89.76,101.14 89.66,101.24 89.66,101.53 89.44,101.75 89.06,101.75 88.84,101.53 88.84,101.24 88.74,101.14 88.54,101.14 88.44,101.24 88.44,101.53 88.22,101.75 87.84,101.75 87.62,101.53 87.62,101.24 87.52,101.14 87.32,101.14 87.22,101.24 87.22,101.53 87,101.75 86.63,101.75 86.4,101.53 86.4,101.24 86.3,101.14 86.1,101.14 86,101.24 86,101.53 85.78,101.75 85.41,101.75 85.19,101.53 85.19,101.24 85.08,101.14 84.88,101.14 84.78,101.24 84.78,101.53 84.56,101.75 84.19,101.75 83.97,101.53 83.97,101.24 83.86,101.14 83.66,101.14 83.56,101.24 83.56,101.53 83.34,101.75 82.97,101.75 82.75,101.53 82.75,101.24 82.65,101.14 82.44,101.14 82.34,101.24 82.34,101.53 82.12,101.75 81.75,101.75 81.53,101.53 81.53,101.24 81.43,101.14 81.22,101.14 81.12,101.24 81.12,101.53 80.9,101.75 80.53,101.75 80.31,101.53 80.31,101.24 80.21,101.14 80,101.14 79.9,101.24 79.9,101.53 79.68,101.75 79.31,101.75 79.09,101.53 79.09,101.24 78.99,101.14 78.78,101.14 78.68,101.24 78.68,101.53 78.46,101.75 78.09,101.75 77.87,101.53 77.87,101.24 77.77,101.14 77.57,101.14 77.46,101.24 77.46,101.53 77.24,101.75 76.87,101.75 76.65,101.53 76.65,101.24 76.55,101.14 76.35,101.14 76.24,101.24 76.24,101.53 76.02,101.75 75.65,101.75 75.43,101.53 75.43,101.24 75.33,101.14 75.13,101.14 75.03,101.24 75.03,101.53 74.81,101.75 74.43,101.75 74.21,101.53 74.21,101.24 74.11,101.14 73.91,101.14 73.81,101.24 73.81,101.53 73.59,101.75 73.21,101.75 72.99,101.53 72.99,101.24 72.89,101.14 72.69,101.14 72.59,101.24 72.59,101.53 72.37,101.75 72,101.75 71.77,101.53 71.77,101.24 71.67,101.14 71.47,101.14 71.37,101.24 71.37,101.53 71.15,101.75 70.78,101.75 70.56,101.53 70.56,101.24 70.45,101.14 70.25,101.14 70.15,101.24 70.15,101.53 69.93,101.75 69.56,101.75 69.34,101.53 69.34,101.24 69.23,101.14 69.03,101.14 68.93,101.24 68.93,101.53 68.71,101.75 68.34,101.75 68.12,101.53 68.12,101.24 68.02,101.14 67.81,101.14 67.71,101.24 67.71,101.53 67.49,101.75 67.12,101.75 66.9,101.53 66.9,101.24 66.8,101.14 66.59,101.14 66.49,101.24 66.49,101.53 66.27,101.75 65.9,101.75 65.68,101.53 65.68,101.24 65.58,101.14 65.37,101.14 65.27,101.24 65.27,101.53 65.05,101.75 64.68,101.75 64.46,101.53 64.46,101.24 64.36,101.14 64.15,101.14 64.05,101.24 64.05,101.53 63.83,101.75 63.46,101.75 63.24,101.53 63.24,101.24 63.14,101.14 62.94,101.14 62.83,101.24 62.83,101.53 62.61,101.75 62.24,101.75 62.02,101.53 62.02,101.24 61.92,101.14 61.72,101.14 61.61,101.24 61.61,101.53 61.39,101.75 61.02,101.75 60.8,101.53 60.8,101.24 60.7,101.14 60.5,101.14 60.4,101.24 60.4,101.56 60.17,101.78 59.8,101.78 59.58,101.56 59.58,101.24 59.48,101.14 59.28,101.14 59.18,101.24 59.18,101.56 58.96,101.78 58.58,101.78 58.36,101.56 58.36,101.24 58.26,101.14 58.06,101.14 57.96,101.24 57.96,101.56 57.74,101.78 57.36,101.78 57.14,101.56 57.14,101.24 57.04,101.14 56.84,101.14 56.74,101.24 56.74,101.56 56.52,101.78 56.15,101.78 55.92,101.56 55.92,101.24 55.82,101.14 55.62,101.14 55.52,101.24 55.52,101.56 55.3,101.78 54.93,101.78 54.71,101.56 54.71,101.24 54.6,101.14 54.4,101.14 54.3,101.24 54.3,101.56 54.08,101.78 53.71,101.78 53.49,101.56 53.49,101.24 53.38,101.14 53.18,101.14 53.08,101.24 53.08,101.56 52.86,101.78 52.49,101.78 52.27,101.56 52.27,101.24 52.17,101.14 51.96,101.14 51.86,101.24 51.86,101.56 51.64,101.78 51.27,101.78 51.05,101.56 51.05,101.24 50.95,101.14 50.74,101.14 50.64,101.24 50.64,101.56 50.42,101.78 50.05,101.78 49.83,101.56 49.83,101.24 49.73,101.14 49.52,101.14 49.42,101.24 49.42,101.56 49.2,101.78 48.83,101.78 48.61,101.56 48.61,101.24 48.51,101.14 48.3,101.14 48.2,101.24 48.2,101.56 47.98,101.78 47.61,101.78 47.39,101.56 47.39,101.24 47.29,101.14 47.09,101.14 46.98,101.24 46.98,101.56 46.76,101.78 46.39,101.78 46.17,101.56 46.17,101.24 46.07,101.14 15.14,101.14 v3(14.61,101.68)
  BOTTOM w0.102: FMC.G25 v3(14.61,101.68)
